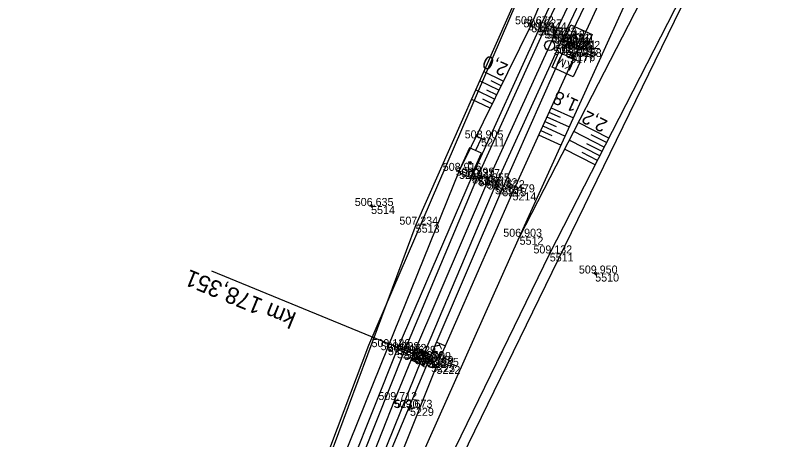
# Model space of a CAD drawing. Extents: x -1234191 to 23050, y -1290331 to -741191.
# Drawn here: x -865066.7 to -864950.3, y -1104361.6 to -1104298.1 of the extents above; entities that cross this region are included whole.
import ezdxf

# ---------------------------------------------------------------- set-up
doc = ezdxf.new("R2010")
doc.units = 0
for name, color, linetype in [('Vrstva 1', 7, 'Continuous'), ('Vrstva 25', 7, 'Continuous'), ('Vrstva 3', 7, 'Continuous'), ('Vrstva 4', 7, 'Continuous'), ('Vrstva 48', 7, 'Continuous'), ('Vrstva 49', 7, 'Continuous'), ('Vrstva 53', 7, 'Continuous'), ('Vrstva 60', 7, 'Continuous'), ('Vrstva 61', 7, 'Continuous'), ('Vrstva 7', 7, 'Continuous')]:
    doc.layers.add(name, color=color, linetype=linetype)

msp = doc.modelspace()

# ---------------------------------------------------------------- linework, layer by layer
at = {"layer": 'Vrstva 1'}
msp.add_lwpolyline([(-864901.05, -1104121.56), (-864916.57, -1104154.35), (-864925.34, -1104172.89), (-864944, -1104212.34), (-864964.22, -1104254.96), (-864977.42, -1104282.85), (-864985.97, -1104301.05), (-864995.95, -1104322.92), (-865007.04, -1104348.76), (-865009.88, -1104355.68), (-865017.28, -1104374.47), (-865024.91, -1104395.04), (-865030.44, -1104410.81), (-865038.78, -1104436.33), (-865045.69, -1104459.26), (-865049.19, -1104471.62), (-865054.21, -1104490.55), (-865059.55, -1104512.44), (-865064.94, -1104536.85), (-865071.03, -1104567.67), (-865074.71, -1104586.54), (-865078.31, -1104602.83), (-865080.55, -1104611.72)], dxfattribs=at)
at = {"layer": 'Vrstva 25'}
msp.add_line((-865004.38, -1104350.25), (-865004.42, -1104350.35), dxfattribs=at)
msp.add_circle((-865004.4, -1104350.3), 0.5, dxfattribs=at)
at = {"layer": 'Vrstva 3'}
for p, q in [((-865037.34, -1104336.33), (-865007.04, -1104348.77)), ((-865006.55, -1104350.04), (-865007.06, -1104348.81)), ((-865006.06, -1104350.24), (-865006.86, -1104348.32)), ((-865005.57, -1104350.44), (-865006.66, -1104347.83)), ((-865005.36, -1104349.95), (-865006.17, -1104348.03)), ((-865005.16, -1104349.46), (-865005.67, -1104348.23)), ((-865004.96, -1104348.97), (-865005.18, -1104348.44)), ((-865007.04, -1104349.84), (-865007.26, -1104349.3))]:
    msp.add_line(p, q, dxfattribs=at)
msp.add_lwpolyline([(-865007.42, -1104349.68), (-865006.66, -1104347.83), (-865004.81, -1104348.59), (-865005.57, -1104350.44)], close=True, dxfattribs=at)
at = {"layer": 'Vrstva 4'}
for points in [[(-865072.4, -1104567.62), (-865066.46, -1104536.55), (-865060.91, -1104512.07), (-865055.71, -1104490.15), (-865047.07, -1104458.86), (-865040.49, -1104436.07), (-865031.89, -1104410.42), (-865026.4, -1104394.39), (-865018.69, -1104374.19), (-865008.48, -1104348.47), (-864997.44, -1104322.28), (-864987.45, -1104300.28), (-864978.8, -1104282.1), (-864965.65, -1104254.25), (-864945.17, -1104211.78), (-864926.83, -1104172.02), (-864918.06, -1104153.79), (-864902.69, -1104120.73)], [(-865063.7, -1104537.31), (-865058.33, -1104512.88), (-865052.98, -1104490.86), (-865044.47, -1104459.65), (-865037.18, -1104436.78), (-865029.25, -1104411.19), (-865023.73, -1104395.55), (-865016.12, -1104375), (-865005.81, -1104349.55), (-864994.84, -1104323.64), (-864984.72, -1104301.52), (-864976.23, -1104283.48), (-864963.04, -1104255.58), (-864942.72, -1104212.72), (-864924.21, -1104173.38), (-864915.11, -1104155.04), (-864899.79, -1104122.19)], [(-864927.54, -1104171.55), (-864946.12, -1104211.02), (-864966.4, -1104253.75), (-864979.69, -1104281.62), (-864988.12, -1104299.83), (-864998.27, -1104322.06), (-865009.53, -1104348.21), (-865019.8, -1104373.88), (-865026.9, -1104394), (-865032.82, -1104410.33), (-865041.15, -1104435.8), (-865048.08, -1104458.42), (-865056.83, -1104489.93), (-865059.48, -1104500.62), (-865060.44, -1104503.62), (-865062.38, -1104511.94), (-865067.15, -1104536.52), (-865073.39, -1104567.62)], [(-864923.23, -1104173.56), (-864941.76, -1104213.42), (-864962.13, -1104256.07), (-864975.47, -1104284.28), (-864983.98, -1104301.96), (-864993.74, -1104323.94), (-865004.78, -1104349.67), (-865015.47, -1104375.17), (-865023.03, -1104395.77), (-865028.56, -1104411.62), (-865036.84, -1104436.96), (-865043.65, -1104459.83), (-865052.05, -1104491.02), (-865057.32, -1104513.2), (-865062.71, -1104537.53)]]:
    msp.add_lwpolyline(points, dxfattribs=at)
at = {"layer": 'Vrstva 48'}
for p, q in [((-864993.6, -1104307.92), (-864996.56, -1104306.46)), ((-864994.27, -1104309.27), (-864997.17, -1104307.84)), ((-864993.94, -1104308.59), (-864995.4, -1104307.87)), ((-864994.93, -1104310.61), (-864997.78, -1104309.21)), ((-864994.6, -1104309.94), (-864996.04, -1104309.23)), ((-864995.59, -1104311.96), (-864998.39, -1104310.58)), ((-864995.26, -1104311.28), (-864996.67, -1104310.59)), ((-864986.75, -1104312.55), (-864985.07, -1104313.31)), ((-864986.44, -1104311.87), (-864983.08, -1104313.4)), ((-864987.37, -1104313.92), (-864985.69, -1104314.68)), ((-864987.06, -1104313.23), (-864983.7, -1104314.76)), ((-864987.68, -1104314.6), (-864984.32, -1104316.13)), ((-864977.78, -1104316.44), (-864982.36, -1104314.09)), ((-864988.31, -1104315.96), (-864984.94, -1104317.5)), ((-864987.99, -1104315.28), (-864986.31, -1104316.05)), ((-864978.46, -1104317.77), (-864983.05, -1104315.42)), ((-864978.12, -1104317.11), (-864980.41, -1104315.93)), ((-864979.14, -1104319.11), (-864983.73, -1104316.76)), ((-864978.8, -1104318.44), (-864981.09, -1104317.27)), ((-864979.83, -1104320.44), (-864984.42, -1104318.09)), ((-864979.49, -1104319.78), (-864981.78, -1104318.6))]:
    msp.add_line(p, q, dxfattribs=at)
at = {"layer": 'Vrstva 49'}
for p, q in [((-865013.18, -1104326.5), (-865013.64, -1104326.69)), ((-865013.5, -1104326.36), (-865013.32, -1104326.83)), ((-864979.58, -1104336.63), (-864980.05, -1104336.81)), ((-864979.91, -1104336.49), (-864979.72, -1104336.95))]:
    msp.add_line(p, q, dxfattribs=at)
for points in [[(-864935.58, -1104156.8), (-864944.82, -1104182.47), (-864954.21, -1104206.46), (-864963.29, -1104228.96), (-864976.25, -1104258.99), (-864991.19, -1104294.33), (-865006.72, -1104329.4), (-865022.65, -1104372.26), (-865028.38, -1104385.11), (-865032.89, -1104387.41)], [(-864922.27, -1104160.16), (-864923.4, -1104160.29), (-864928.67, -1104171), (-864947.43, -1104210.44), (-864967.55, -1104251.9), (-864981.45, -1104280.35), (-864989.39, -1104299.38), (-865000.22, -1104321.34), (-865010.89, -1104347.75), (-865021.25, -1104373.36), (-865029.5, -1104393.05), (-865035.39, -1104410.58), (-865042.96, -1104436.64), (-865049.29, -1104458.04), (-865053.07, -1104471.22), (-865053.07, -1104471.22)], [(-864940.93, -1104214.17), (-864960.99, -1104256.7), (-864973.88, -1104284.51), (-864982.43, -1104303.07), (-864992.22, -1104324.56), (-865003.61, -1104350.56), (-865013.69, -1104375.8), (-865021.56, -1104396.22), (-865026.38, -1104412.56), (-865034.77, -1104437.63), (-865041.68, -1104460.85), (-865049.75, -1104491.57), (-865055.79, -1104513.43), (-865060.82, -1104538), (-865066.78, -1104568.18), (-865071.36, -1104587.44)], [(-865019.71, -1104399.4), (-865006.1, -1104364.69), (-864991.15, -1104331.21), (-864973.33, -1104291.86), (-864952.62, -1104251.6), (-864937.31, -1104220.86), (-864949.66, -1104252.33), (-864971.23, -1104292.42), (-864991.15, -1104331.21)], [(-865065.29, -1104601.64), (-865064.45, -1104598.98), (-865057.28, -1104568.8), (-865052.09, -1104539.62), (-865047.81, -1104514.63), (-865044.23, -1104493.03), (-865034.97, -1104457.38), (-865026.8, -1104431.72), (-865014.98, -1104397.76), (-865002.57, -1104366.47), (-864986.63, -1104333.71), (-864966.82, -1104295.07), (-864945.18, -1104253.25)]]:
    msp.add_lwpolyline(points, dxfattribs=at)
at = {"layer": 'Vrstva 53'}
for points in [[(-864807.11, -1103958.19), (-864822.22, -1104000.51), (-864835.28, -1104037.32), (-864838.01, -1104046.95), (-864851.71, -1104040.76), (-864863.24, -1104063.67), (-864844.61, -1104073.61), (-864887.12, -1104118.02), (-864905.23, -1104169.34), (-864947.72, -1104257.32), (-865004.66, -1104374.19), (-865032.1, -1104446.33), (-865047.81, -1104514.61), (-865065.29, -1104601.64)], [(-865075.53, -1104555.37), (-865046.62, -1104434.51), (-865013.74, -1104347.44), (-864969.42, -1104244.67), (-864930.6, -1104141.92), (-864898.82, -1104101.19), (-864887.78, -1104038.43), (-864851.8, -1103965.2)]]:
    msp.add_lwpolyline(points, dxfattribs=at)
at = {"layer": 'Vrstva 60'}
for p, q in [((-864989.39, -1104299.38), (-864989.39, -1104299.38)), ((-864988.12, -1104299.83), (-864988.12, -1104299.83)), ((-864987.45, -1104300.28), (-864987.45, -1104300.28)), ((-864985.97, -1104301.05), (-864985.97, -1104301.05)), ((-864984.72, -1104301.52), (-864984.72, -1104301.52)), ((-864983.98, -1104301.96), (-864983.98, -1104301.96)), ((-864983.57, -1104302.07), (-864983.57, -1104302.07)), ((-864983.17, -1104302.99), (-864983.17, -1104302.99)), ((-864982.43, -1104303.07), (-864982.43, -1104303.07)), ((-864983.58, -1104303.95), (-864983.58, -1104303.95)), ((-864983.4, -1104303.7), (-864983.4, -1104303.7)), ((-864996.93, -1104316.47), (-864996.93, -1104316.47)), ((-865000.22, -1104321.34), (-865000.22, -1104321.34)), ((-864998.27, -1104322.06), (-864998.27, -1104322.06)), ((-864997.44, -1104322.28), (-864997.44, -1104322.28)), ((-864995.95, -1104322.92), (-864995.95, -1104322.92)), ((-864994.84, -1104323.64), (-864994.84, -1104323.64)), ((-864993.74, -1104323.94), (-864993.74, -1104323.94)), ((-864992.22, -1104324.56), (-864992.22, -1104324.56)), ((-865013.41, -1104326.6), (-865013.41, -1104326.6)), ((-865006.72, -1104329.4), (-865006.72, -1104329.4)), ((-864991.15, -1104331.21), (-864991.15, -1104331.21)), ((-864986.63, -1104333.71), (-864986.63, -1104333.71)), ((-864979.82, -1104336.72), (-864979.82, -1104336.72)), ((-865010.89, -1104347.75), (-865010.89, -1104347.75)), ((-865009.53, -1104348.21), (-865009.53, -1104348.21)), ((-865008.48, -1104348.47), (-865008.48, -1104348.47)), ((-865007.04, -1104348.76), (-865007.04, -1104348.76)), ((-865005.81, -1104349.55), (-865005.81, -1104349.55)), ((-865004.78, -1104349.67), (-865004.78, -1104349.67)), ((-865004.4, -1104350.3), (-865004.4, -1104350.3)), ((-865003.61, -1104350.56), (-865003.61, -1104350.56)), ((-865009.88, -1104355.68), (-865009.88, -1104355.68)), ((-865007.58, -1104356.84), (-865007.58, -1104356.84))]:
    msp.add_line(p, q, dxfattribs=at)
at = {"layer": 'Vrstva 7'}
for p, q in [((-864983.11, -1104302.29), (-864984.02, -1104301.86)), ((-864983.35, -1104301.62), (-864983.78, -1104302.53)), ((-864983.17, -1104302.99), (-864982.91, -1104302.42)), ((-864983.4, -1104303.7), (-864983.66, -1104304.26)), ((-864983.56, -1104303.91), (-864983.6, -1104304)), ((-864996.24, -1104316.78), (-864997.61, -1104316.16)), ((-864998.77, -1104320.18), (-864998.4, -1104320.04)), ((-865007.12, -1104357.02), (-865008.05, -1104356.66)), ((-865007.4, -1104356.37), (-865007.77, -1104357.31))]:
    msp.add_line(p, q, dxfattribs=at)
for points in [[(-864984.5, -1104301.7), (-864983.47, -1104299.44), (-864980.29, -1104300.89), (-864981.32, -1104303.15)], [(-864982.08, -1104304.99), (-864983.11, -1104307.24), (-864986.28, -1104305.8), (-864985.25, -1104303.54)]]:
    msp.add_lwpolyline(points, close=True, dxfattribs=at)
msp.add_lwpolyline([(-864996.93, -1104316.47), (-864997.76, -1104318.29), (-864998.67, -1104317.87), (-865000.33, -1104321.51), (-864998.51, -1104322.34), (-864996.85, -1104318.7), (-864997.76, -1104318.29)], dxfattribs=at)
for centre, radius in [((-864986.65, -1104302.55), 0.75), ((-864983.58, -1104303.95), 0.5), ((-864998.59, -1104320.11), 0.2)]:
    msp.add_circle(centre, radius, dxfattribs=at)

# ---------------------------------------------------------------- texts
at = {"layer": 'Vrstva 25'}
msp.add_text('k.o.', height=1.5, rotation=247.6807, dxfattribs=at).set_placement((-865003.56, -1104346.79))
at = {"layer": 'Vrstva 3'}
msp.add_text('km 178,351', height=2.5, rotation=157.6807, dxfattribs=at).set_placement((-865024.47, -1104342.69))
at = {"layer": 'Vrstva 48'}
for s, rotation, p in [('2,0', 156.1167, (-864992.73, -1104305.44)), ('1,8', 155.6281, (-864982.17, -1104310.82)), ('2,2', 152.8578, (-864977.82, -1104313.9))]:
    msp.add_text(s, height=2, rotation=rotation, dxfattribs=at).set_placement(p)
at = {"layer": 'Vrstva 60'}
for s, p in [('5174', (-864989.39, -1104300.57)), ('5173', (-864988.12, -1104301.03)), ('5172', (-864987.45, -1104301.48)), ('5166', (-864985.97, -1104302.25)), ('5171', (-864984.72, -1104302.72)), ('5170', (-864983.98, -1104303.16)), ('5169', (-864983.57, -1104303.27)), ('5175', (-864983.17, -1104304.19)), ('5168', (-864982.43, -1104304.27)), ('5177', (-864983.58, -1104305.15)), ('5176', (-864983.4, -1104304.9)), ('5211', (-864996.93, -1104317.67)), ('5219', (-865000.22, -1104322.54)), ('5218', (-864998.27, -1104323.26)), ('5217', (-864997.44, -1104323.48)), ('5212', (-864995.95, -1104324.12)), ('5216', (-864994.84, -1104324.84)), ('5215', (-864993.74, -1104325.14)), ('5214', (-864992.22, -1104325.76)), ('5514', (-865013.41, -1104327.8)), ('5513', (-865006.72, -1104330.6)), ('5512', (-864991.15, -1104332.41)), ('5511', (-864986.63, -1104334.91)), ('5510', (-864979.82, -1104337.92)), ('5228', (-865010.89, -1104348.95)), ('5227', (-865009.53, -1104349.41)), ('5226', (-865008.48, -1104349.67)), ('5220', (-865007.04, -1104349.96)), ('5225', (-865005.81, -1104350.76)), ('5224', (-865004.78, -1104350.87)), ('5223', (-865004.4, -1104351.5)), ('5222', (-865003.61, -1104351.76)), ('5230', (-865009.88, -1104356.88)), ('5229', (-865007.58, -1104358.04))]:
    msp.add_text(s, height=1.2, dxfattribs=at).set_placement(p)
at = {"layer": 'Vrstva 61'}
for s, p in [('508.672', (-864991.84, -1104299.38)), ('508.627', (-864990.58, -1104299.83)), ('508.944', (-864989.9, -1104300.28)), ('509.123', (-864988.42, -1104301.05)), ('508.918', (-864987.18, -1104301.52)), ('508.521', (-864986.34, -1104301.96)), ('509.019', (-864986.02, -1104302.07)), ('508.351', (-864985.53, -1104302.99)), ('508.302', (-864984.88, -1104303.07)), ('508.719', (-864986.04, -1104303.95)), ('508.361', (-864985.76, -1104303.7)), ('508.905', (-864999.38, -1104316.47)), ('508.916', (-865002.67, -1104321.34)), ('508.899', (-865000.73, -1104322.06)), ('509.217', (-864999.89, -1104322.28)), ('509.355', (-864998.41, -1104322.92)), ('509.122', (-864997.29, -1104323.64)), ('508.622', (-864996.19, -1104323.94)), ('508.479', (-864994.68, -1104324.56)), ('506.635', (-865015.86, -1104326.6)), ('507.234', (-865009.17, -1104329.4)), ('506.903', (-864993.6, -1104331.21)), ('509.132', (-864989.08, -1104333.71)), ('509.950', (-864982.27, -1104336.72)), ('509.126', (-865013.35, -1104347.75)), ('509.088', (-865011.98, -1104348.21)), ('509.472', (-865010.93, -1104348.47)), ('509.629', (-865009.49, -1104348.76)), ('509.276', (-865008.26, -1104349.55)), ('508.909', (-865007.24, -1104349.67)), ('509.149', (-865006.85, -1104350.3)), ('508.885', (-865006.07, -1104350.56)), ('509.712', (-865012.32, -1104355.68)), ('509.673', (-865010.03, -1104356.84))]:
    msp.add_text(s, height=1.2, dxfattribs=at).set_placement(p)
at = {"layer": 'Vrstva 7'}
for rotation, p in [(335.4752, (-864983.58, -1104301.44)), (155.4752, (-864982.99, -1104305.25))]:
    msp.add_text('KM', height=1.247, rotation=rotation, dxfattribs=at).set_placement(p)

doc.saveas('drawing.dxf')
